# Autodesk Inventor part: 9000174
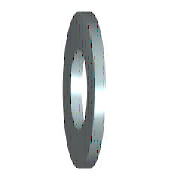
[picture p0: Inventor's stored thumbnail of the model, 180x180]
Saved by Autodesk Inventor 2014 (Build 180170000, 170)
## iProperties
Created: 2011-02
Material: Steel, Mild
Description: WASHER, FLAT 1/2"
Document SubType Name: Modeling
Standard: ASTM F436
Designer: Dave Walker
Standard Revision: 2004
Standards Organization: ANSI
Language: en-US
Size Designation: 1/2
Categories: <MemberInstance><Categories><Category DisplayName="Fasteners" InternalName="e4da775c-781d-43d5-af7c-5136215cf5a6" Mnemonic="FSTN"><Category DisplayName="Washers
Density: 7.86 g/cm^3
Part Number: 9000174
Mass: 15.184 g
Surface Area: 14.3123 cm^2
Volume: 1.93181 cm^3
Appearance: Steel
IsCustomPart: 1
Author: Dave Walker
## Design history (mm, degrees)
sketch "Sketch"
  geometry: C1 r 13.5 at (0, 0); C2 r 6.744 at (0, 0); 1 further point
  constraints: 2 centre point, 2 coincident
  dimensions: "d0" = 13.4874 diameter of C2 (= SD1); "d1" = 27.0002 diameter of C1 (= SD2)
extrude "Body" new body sketch "Sketch" distance "d2" = 4.4958 (= SD); taper "d3" = 0 deg
workaxis "Work Axis1"
workplane "Work Plane1"
body "Solid1"
other parameters: "SD1" = 13.4874 [user parameter; used in 1 equation term], "SD2" = 27.0002 [user parameter; used in 1 equation term], "SD" = 4.4958 [user parameter; used in 1 equation term], "d4" = 0, "d5" = 0, "d6" = 0, "d7" = 0, "NND" = 12.7 [user parameter]
